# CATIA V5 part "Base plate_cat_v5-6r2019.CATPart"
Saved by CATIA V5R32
Part number: Base Plate
Bounding box of the stored display mesh (mm): x -10 to 10, y 0 to 144, z 0 to 6
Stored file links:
  D:\PROJECTS\Project 2022\CATIA V5 6R 2022\Resources\Tutorial Files\c16_catia_v5_6r2022_tut\Bench vice\Base plate_cat_v5-6r2019.CATPart
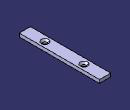
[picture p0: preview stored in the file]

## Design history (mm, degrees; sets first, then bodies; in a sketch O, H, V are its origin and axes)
Body1 (main body)
  Sketch1 on zx-plane, origin (0, 0, 0), H (-1, 0, 0), V (0, 0, 1)
    point P1 (-10, 0)
    line L1 (-10, 0) -> (10, 0)
    line L2 (10, 0) -> (10, 6)
    line L3 (10, 6) -> (-10, 6)
    line L4 (-10, 6) -> (-10, 0)
    length L3 = 20
    length L2 = 6
    distance V L2 = 10
    coincidence: P1 H
    horizontal: L1 H, L3 H
    vertical: L2 V, L4 V
  Pad1: profile Sketch1, direction (0, 1, 0), length 144
  Sketch2 on face of Pad1, origin (-6.0071, 115.251, 6), H (1, 0, 0), V (0, 1, 0)
    point P1 (6.0071, -9.251)
    reference projected line E1 (-3.9929, -115.251) -> (-3.9929, 28.749) from edge of Pad1
    reference projected line E2 (16.0071, 28.749) -> (-3.9929, 28.749) from edge of Pad1
    distance E1 P1 = 10
    distance E2 P1 = 38
  Hole1: placed by Sketch2, at (0, 106, 6) direction (0, 0, -1), diameter 7, through (limit type 6), countersink depth 3, countersink angle 90
  RectPattern1: of Hole1, direction 1 instances 2, spacing 70, along edge of Pad1 reversed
